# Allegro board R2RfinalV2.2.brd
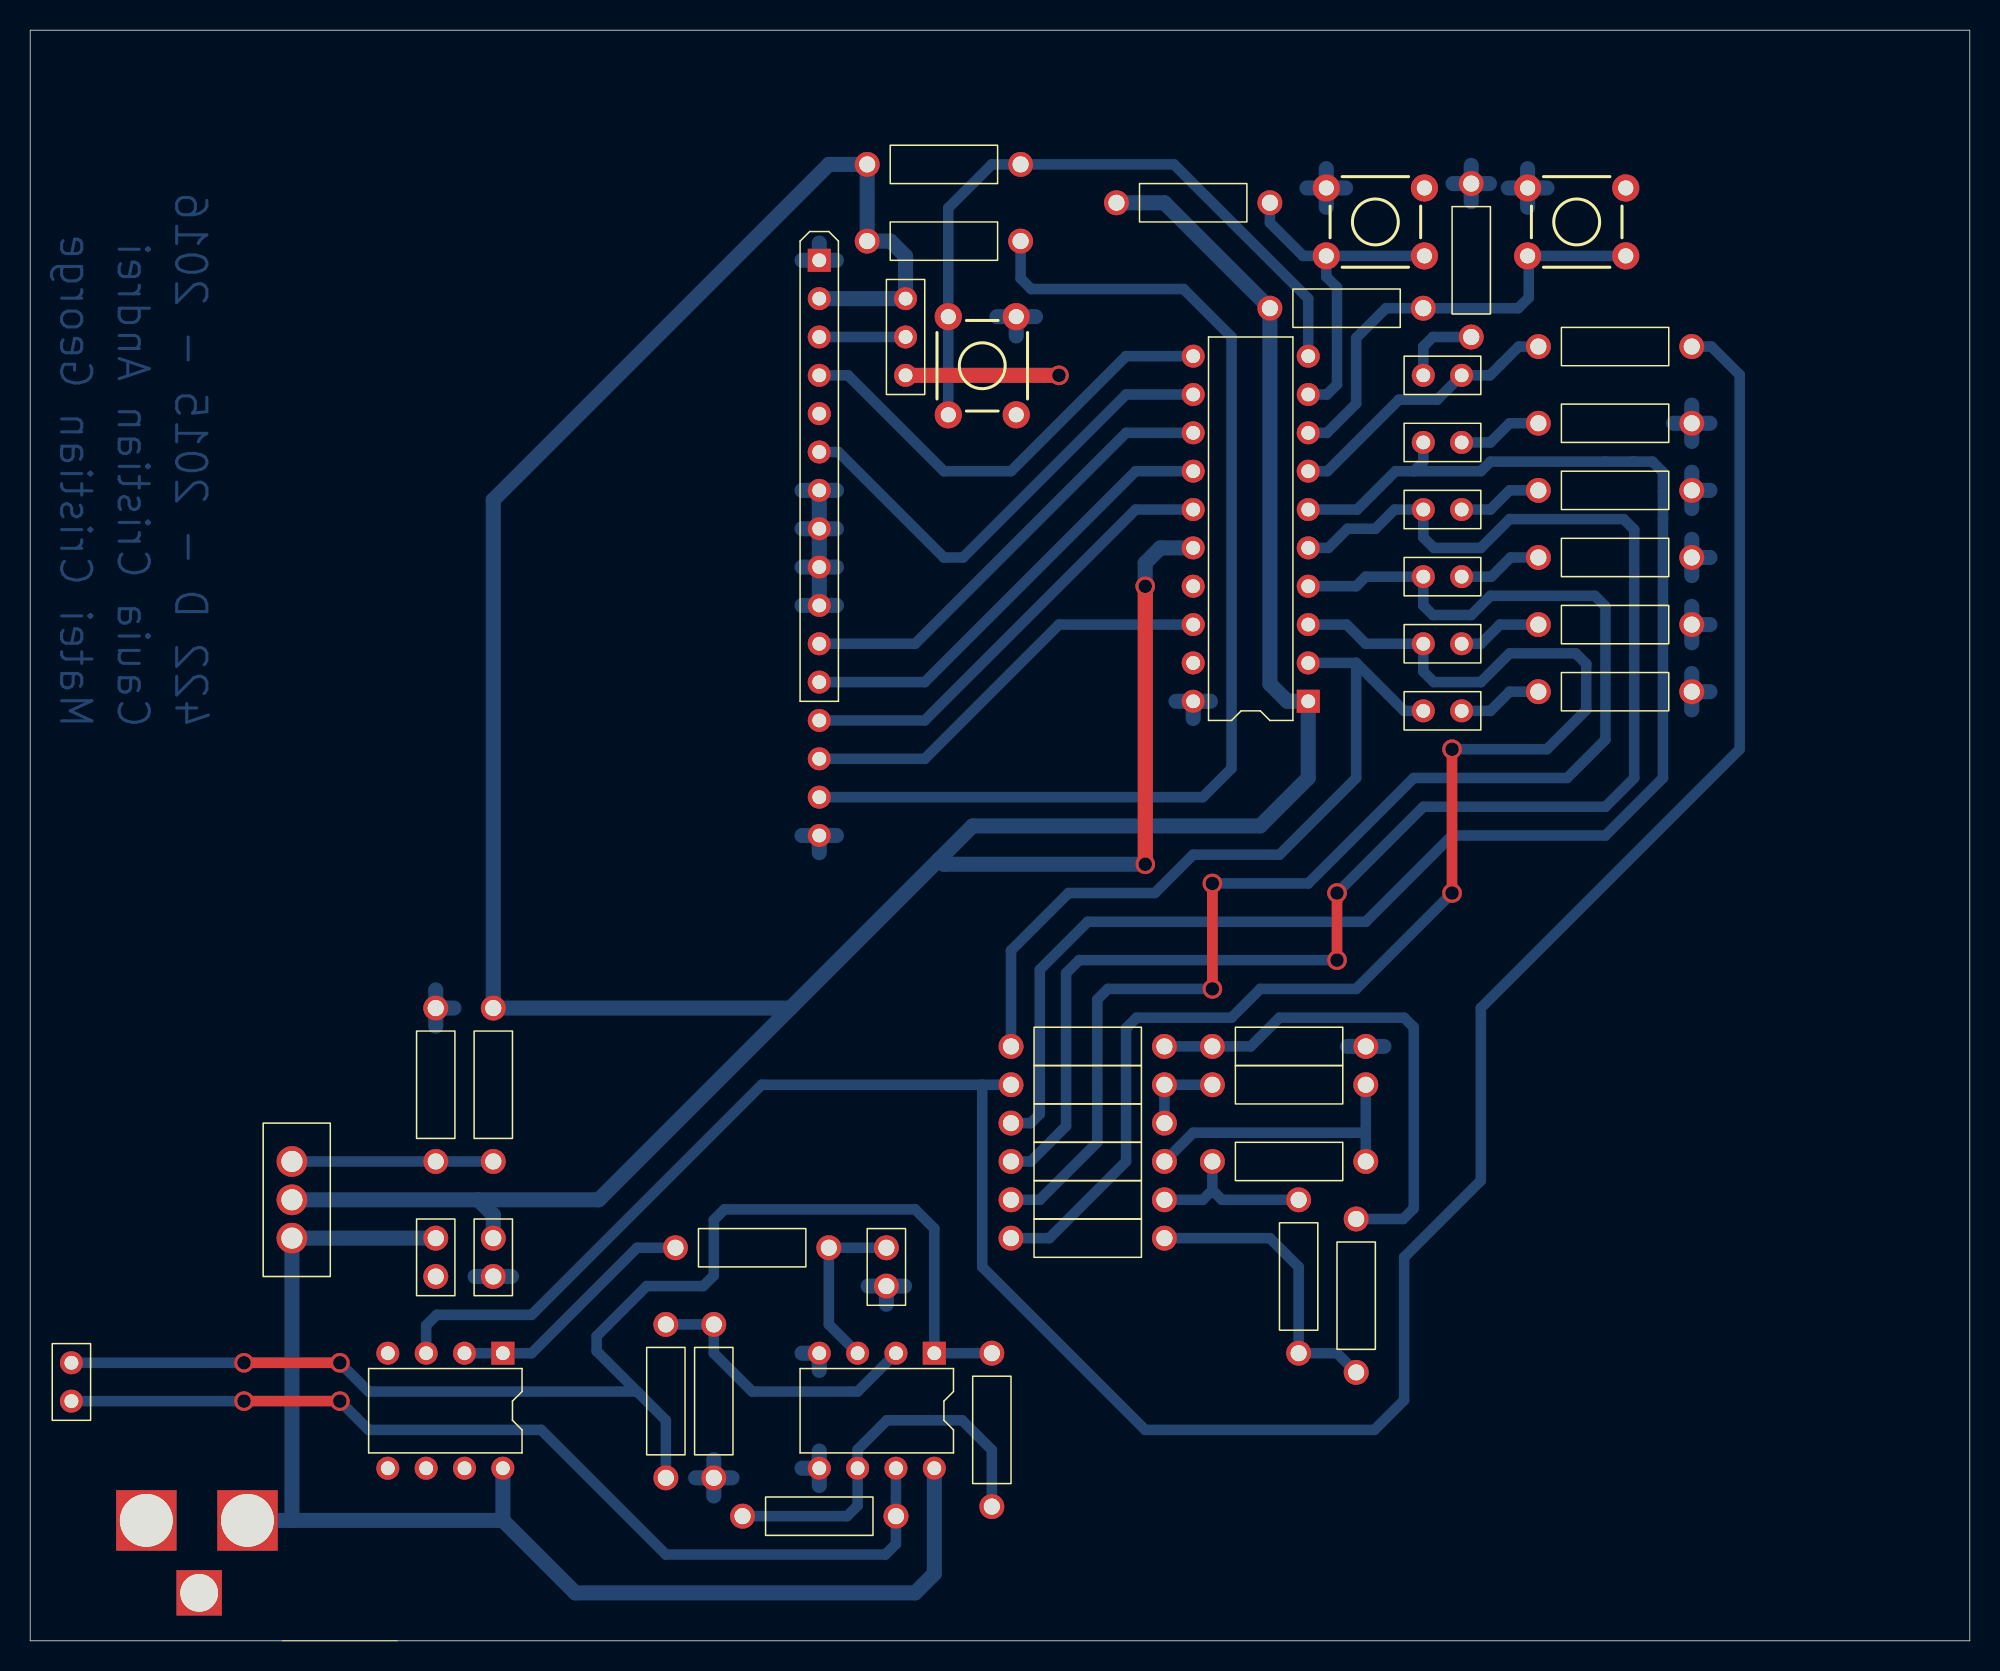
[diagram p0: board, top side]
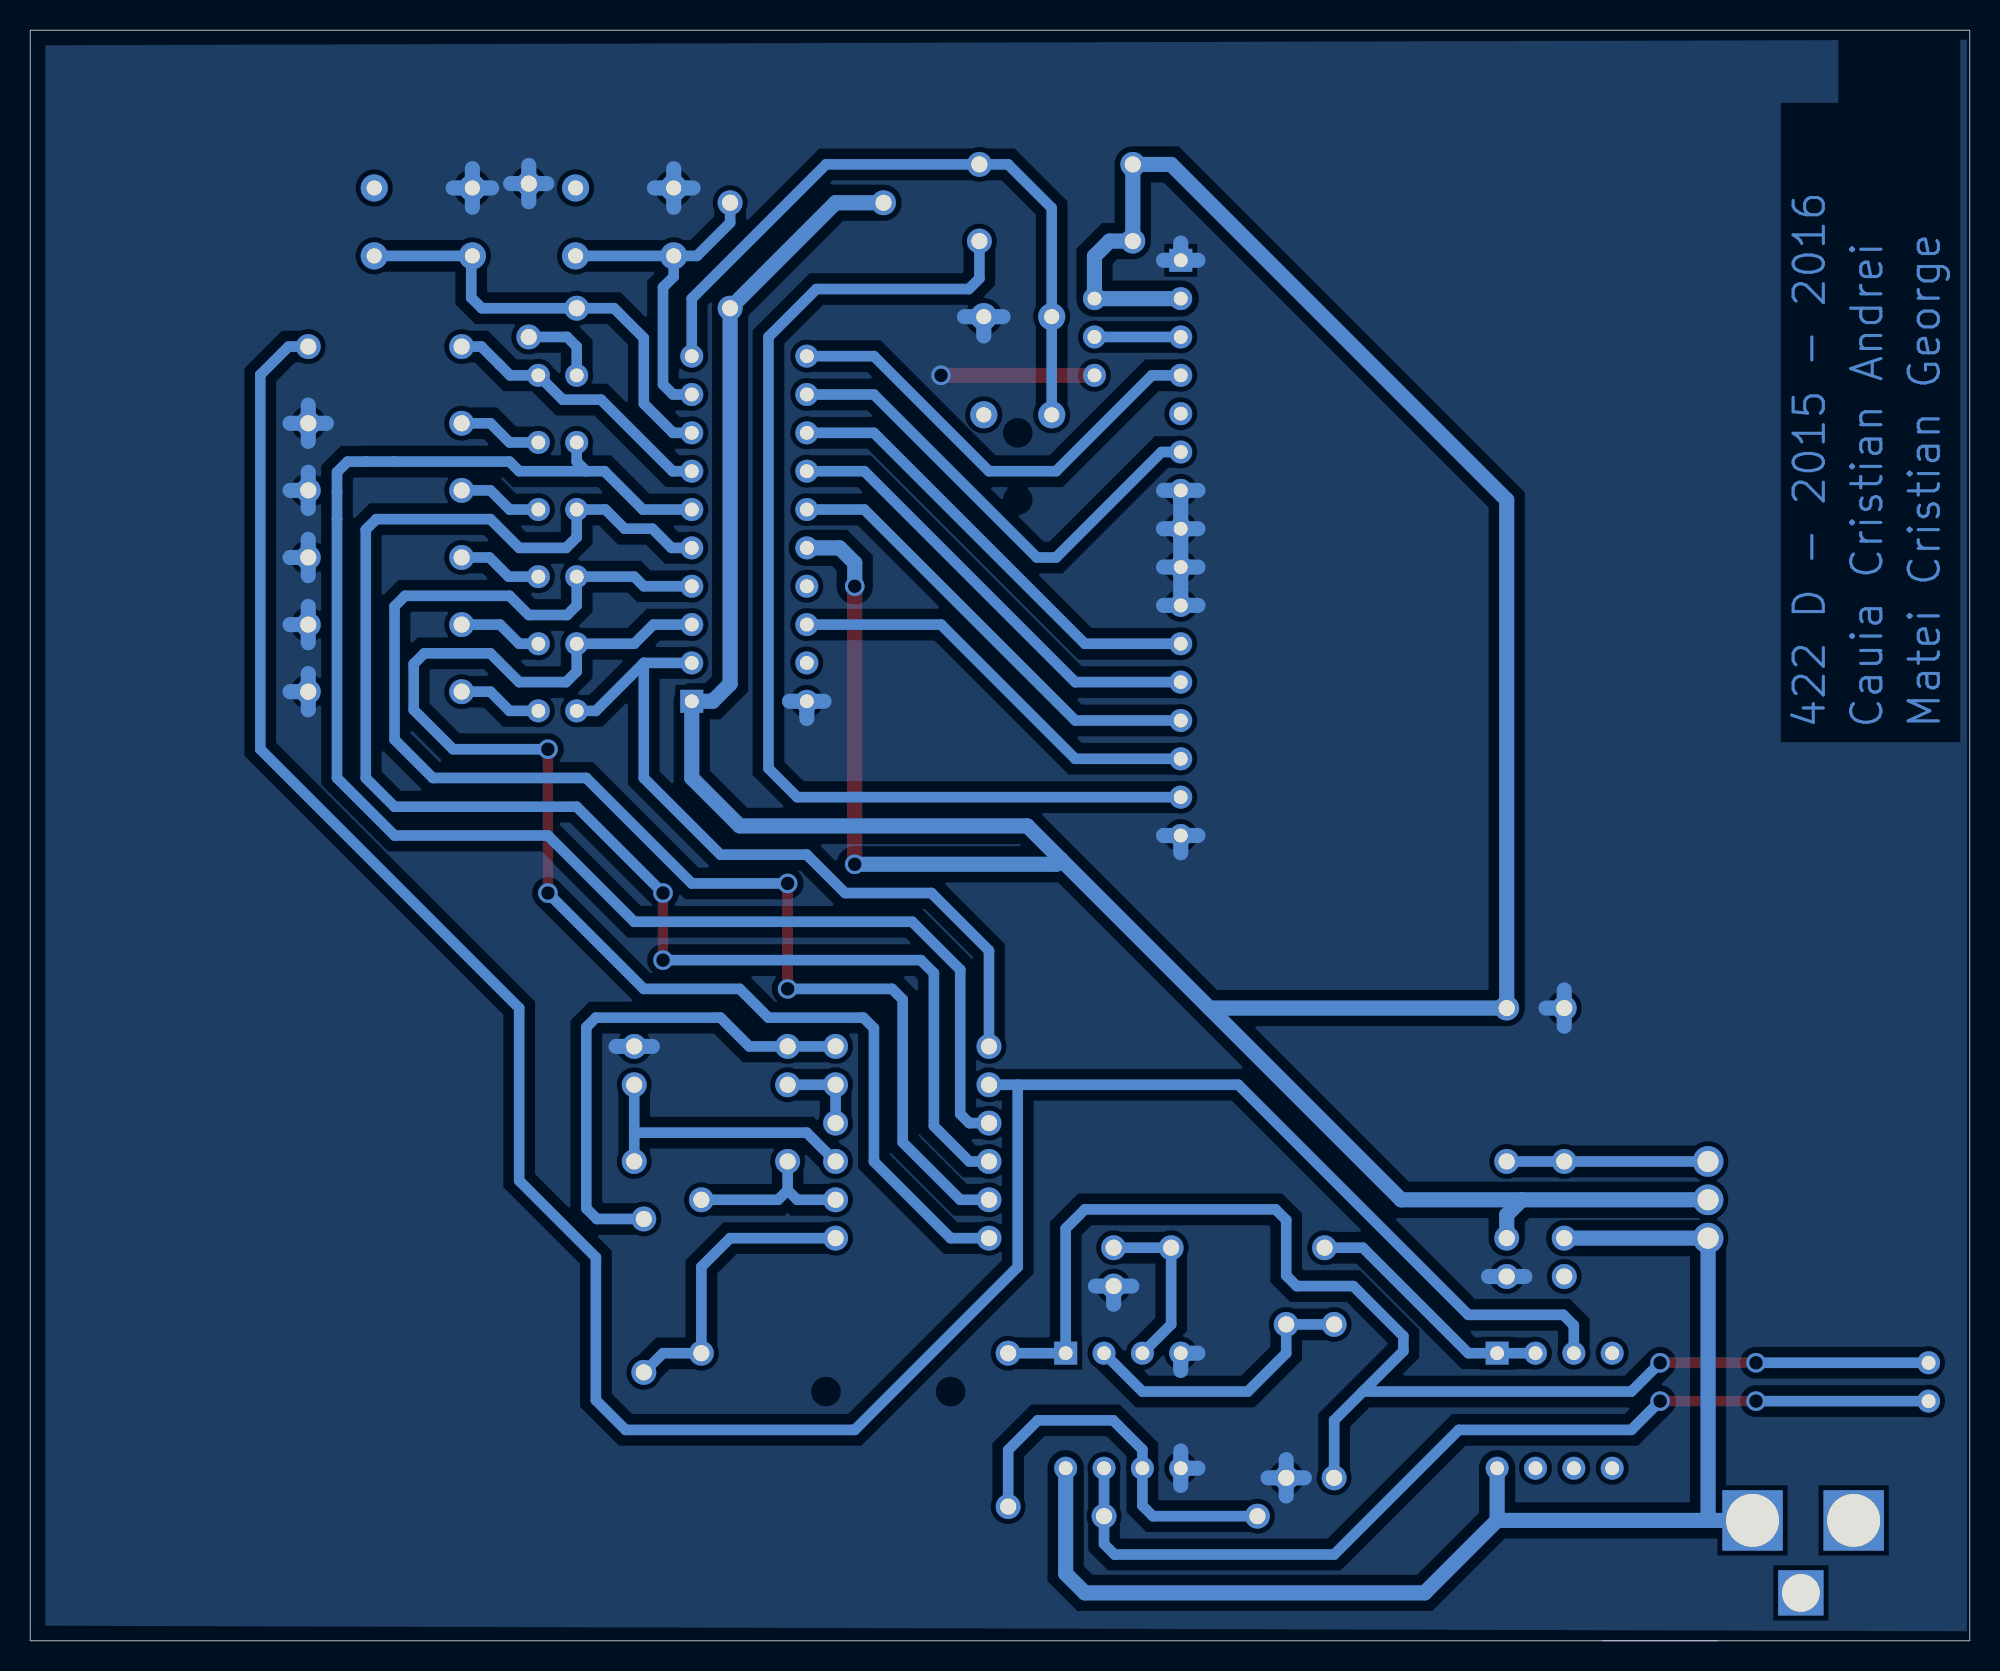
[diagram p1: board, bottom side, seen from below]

Outline 128.46 x 106.68 mm; copper layers: TOP, BOTTOM. Coordinates in mm from the lower left corner of the outline.
Outline path: 24.32,0 0,0 0,106.68 128.46,106.68 128.46,0 16.7,0

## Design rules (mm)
net group VCC: nets N20855 N35721 SW1 SW2 SW3 VCC
nets with their own width: min track width 0.7; nets N00328 N00336 N00340 N00355 N00395 N00470 N01662 N01669 N01683 N01690 N01717 N006340 N006500 N006660 N006820 N006980 N007140 N23488 N23661 N24189 N24193 N25824 N25853 N29134 N35057 N35516 N35592 N35638 N35656 N35674 N35692
nets with their own width: min track width 1; nets 0 9V

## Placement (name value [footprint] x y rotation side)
C3  10nf  [CAPCK05]  56.7 26.04 180 top
C4  10u  [CAPCK05]  26.86 24.13 0 top
C5  10u  [CAPCK05]  30.67 24.13 0 top
D1  MLED81  [JUMPER2]  94.81 83.82 180 top
D2  MLED81  [JUMPER2]  92.26 79.38 0 top
D3  MLED81  [JUMPER2]  92.26 74.93 0 top
D4  MLED81  [JUMPER2]  92.26 70.49 0 top
D5  MLED81  [JUMPER2]  92.26 66.04 0 top
D6  MLED81  [JUMPER2]  92.26 61.6 0 top
J1  Speaker  [JUMPER2]  2.73 18.42 270 top
J2  LCD 1602  [SIP16]  52.26 91.44 0 top
J3  CON3  [JACK_DC2]  0.19 3.18 0 top
R2  1k  [RES400]  75.12 36.83 90 top
R3  1k  [RES400]  88.45 36.83 90 top
R4  1k  [RES400]  78.3 31.75 270 top
R5  1k  [RES400]  84.01 19.05 0 top
R6  1k  [RES400]  87.82 27.94 180 top
R7  2k  [RES400]  64.96 39.37 270 top
R8  2k  [RES400]  64.96 26.67 270 top
R9  2k  [RES400]  64.96 29.21 270 top
R10  2k  [RES400]  64.96 31.75 270 top
R11  2k  [RES400]  64.96 34.29 270 top
R12  2k  [RES400]  99.88 85.73 270 top
R13  2k  [RES400]  88.45 39.37 90 top
R14  470  [RES400]  110.05 62.87 90 top
R15  470  [RES400]  110.05 67.31 90 top
R16  470  [RES400]  110.05 71.75 90 top
R17  470  [RES400]  110.05 76.2 90 top
R18  470  [RES400]  110.05 80.65 90 top
R19  470  [RES400]  95.44 96.52 180 top
R20  10k  [RES400]  45.27 20.96 180 top
R22  10k  [RES400]  63.69 8.89 0 top
R23  1k  [RES400]  26.86 41.91 180 top
R24  470  [RES400]  30.67 31.75 0 top
R26  33k  [RES400]  42.74 26.04 270 top
R27  10k  [RES400]  42.1 10.8 0 top
R28  10k  [RES400]  57.34 8.25 90 top
R29  1k  [JUMPER3]  57.98 83.82 90 top
R30  10k  [RES400]  65.6 97.79 90 top
R33  1k  [RES400]  55.44 92.71 270 top
R34  10k  [RES400]  82.11 95.25 90 top
R35  10k  [RES400]  92.26 88.27 90 top
SW7  SW_TC_SPST  [SW_SCHURTER_13019306L]  63.06 84.46 0 top
SW8  SW_TC_SPST  [SW_SCHURTER_13019306L]  89.09 93.98 90 top
SW9  SW_TC_SPST  [SW_SCHURTER_13019306L]  102.43 93.98 90 top
U1  MSP430G2553  [DIP20]  84.64 62.23 180 top
U7  LM317K  [TO220AB]  17.33 31.75 90 top
U9  LM358  [DIP8_3]  59.88 19.05 270 top
U10  LM358  [DIP8_3]  31.31 19.05 270 top

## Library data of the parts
C3 = C: Tolerance: ***; User Part Number: ***; signal model: DEFAULT_CAPACITOR_10000pF_1_2
C4 C5 = C: Tolerance: ***; User Part Number: ***; signal model: DEFAULT_CAPACITOR_1e+07pF_1_2
D1-D6 = MLED81: User Part Number: ***
J1 = CON2: User Part Number: ***
J2 = CON16: User Part Number: ***
J3 = CON3
R2-R6 R23 R33 = R: Tolerance: ***; User Part Number: ***; signal model: DEFAULT_RESISTOR_1000OHM_2_1
R7-R13 = R: Tolerance: ***; User Part Number: ***; signal model: DEFAULT_RESISTOR_2000OHM_2_1
R14-R19 R24 = R: Tolerance: ***; User Part Number: ***; signal model: DEFAULT_RESISTOR_470OHM_2_1
R20 R22 R27 R28 R30 R34 R35 = R: Tolerance: ***; User Part Number: ***; signal model: DEFAULT_RESISTOR_10000OHM_2_1
R26 = R: Tolerance: ***; User Part Number: ***; signal model: DEFAULT_RESISTOR_33000OHM_2_1
R29 = POT: User Part Number: ***
SW7-SW9 = SW_TC_SPST
U1 = MSP430G2553_4: Tolerance: ***; User Part Number: ***
U7 = LM317T_0
U9 = LM358: Tolerance: ***; User Part Number: ***
U10 = LM358_0: Tolerance: ***; User Part Number: ***

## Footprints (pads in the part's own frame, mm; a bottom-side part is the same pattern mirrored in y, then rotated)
CAPCK05
  round 1.651 hole 1.067: 1(0,0) 2(0,2.54)
DIP8_3
  rect 1.524x1.524 hole 0.914: 1(0,0)
  round 1.524 hole 0.914: 2(0,-2.54) 3(0,-5.08) 4(0,-7.62) 5(7.62,-7.62) 6(7.62,-5.08) 7(7.62,-2.54) 8(7.62,0)
DIP20
  rect 1.524x1.524 hole 0.914: 1(0,0)
  round 1.524 hole 0.914: 2(0,-2.54) 3(0,-5.08) 4(0,-7.62) 5(0,-10.16) 6(0,-12.7) 7(0,-15.24) 8(0,-17.78) 9(0,-20.32) 10(0,-22.86) 11(7.62,-22.86) 12(7.62,-20.32) 13(7.62,-17.78) 14(7.62,-15.24) 15(7.62,-12.7) 16(7.62,-10.16) 17(7.62,-7.62) 18(7.62,-5.08) 19(7.62,-2.54) 20(7.62,0)
JACK_DC2
  rect 4x4 hole 3.5: 1(14.2,4.8) 2(7.5,4.8)
  rect 3x3 hole 2.5: 3(11,0)
JUMPER2
  round 1.524 hole 0.914: 1(0,0) 2(2.54,0)
JUMPER3
  round 1.524 hole 0.914: 1(0,0) 2(2.54,0) 3(5.08,0)
RES400
  round 1.651 hole 1.067: 1(0,0) 2(0,10.16)
SIP16
  rect 1.524x1.524 hole 0.914: 1(0,0)
  round 1.524 hole 0.914: 2(0,-2.54) 3(0,-5.08) 4(0,-7.62) 5(0,-10.16) 6(0,-12.7) 7(0,-15.24) 8(0,-17.78) 9(0,-20.32) 10(0,-22.86) 11(0,-25.4) 12(0,-27.94) 13(0,-30.48) 14(0,-33.02) 15(0,-35.56) 16(0,-38.1)
SW_SCHURTER_13019306L
  round 1.8 hole 1: 1(-2.25,-3.25) 2(-2.25,3.25) 3(2.25,3.25) 4(2.25,-3.25)
TO220AB
  round 2.032 hole 1.397: 1(0,0) 2(-2.54,0) 3(-5.08,0)

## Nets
9V: C4.2 J3.1 U7.3(OUT) U9.8(V+) U10.8(V+)
VCC: C5.2 J2.2 R24.2 R29.3(2) R30.2 R33.1 R34.2 R35.2 U1.1(DVCC) U1.16(RESET) U7.2(IN)
0: C3.2 C4.1 C5.1 J2.1 J2.5 J2.7 J2.8 J2.9 J2.10 J2.16 J3.2 J3.3 R13.1 R14.1 R15.1 R16.1 R17.1 R18.1 R19.1 R20.2 R23.1 R29.1 SW7.3 SW8.3 SW9.3 U1.20(GROUND) U9.4(V-) U9.5(+) U10.4(V-)
SW1: R30.1 SW7.1 SW7.2 U1.10(P2_2)
SW2: R34.1 SW8.1 SW8.2 U1.9(P2_1)
SW3: R35.1 SW9.1 SW9.2 U1.8(P2_0/CS(B0))
N00328: R2.1 R3.2 R11.2
N00336: R4.1 R5.2 R9.2
N00340: R5.1 R6.2 R8.2
N00355: R2.2 R12.2 U10.3(+)
N00395: R3.1 R4.2 R10.2
N00470: R6.1 R7.2 R13.2
N01662: D5.1(A) R8.1 U1.3(P1_1/A1/RXD)
N01669: D4.1(A) R9.1 U1.4(P1_2/A2/TXD)
N01683: D2.1(A) R11.1 U1.6(P1_4/A4)
N01690: D1.1(A) R12.1 U1.7(P1_5/A5/SCK(B0))
N01717: D3.1(A) R10.1 U1.5(P1_3/A3/PUSH2)
N006340: D6.2(C) R14.2
N006500: D5.2(C) R15.2
N006660: D4.2(C) R16.2
N006820: D3.2(C) R17.2
N006980: D2.2(C) R18.2
N007140: D1.2(C) R19.2
N20855: R23.2 R24.1 U7.1(ADJ)
N23488: C3.1 R26.2 U9.3(+)
N23661: R26.1 U10.1(OUT) U10.2(-)
N24189: R20.1 R27.2 U9.2(-)
N24193: J1.1 R22.2 R27.1 U9.1(OUT)
N25824: R22.1 R28.2 U9.6(-)
N25853: J1.2 R28.1 U9.7(OUT)
N29134: D6.1(A) R7.1 U1.2(P1_0/A0/RED_LED)
N35057: J2.3 R29.2(T)
N35516: J2.4 U1.11(P2_3)
N35592: J2.6 U1.12(P2_4)
N35638: J2.11 U1.13(P2_5)
N35656: J2.12 U1.14(P1_6/A6/SCL/MISO(B0)/GREEN LED)
N35674: J2.13 U1.15(P1_7/A7/SDA/MOSE(B0))
N35692: J2.14 U1.18(P2_7/XOUT)
N35721: J2.15 R33.2

Pads without a net: SW7 4; SW8 4; SW9 4; U1 17 19; U10 5 6 7

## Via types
v1: diameter 1.3, hole 0.9, TOP to BOTTOM, 13 vias

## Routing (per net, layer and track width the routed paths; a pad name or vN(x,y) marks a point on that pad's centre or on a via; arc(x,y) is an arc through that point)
9V: length 86.7
  BOTTOM w1: 17.33,7.98 U7.3 C4.2 ; 17.33,7.98 J3.1 ; 17.33,7.98 31.31,7.98 ; U10.8 31.31,7.98 ; 31.31,7.98 36.11,3.18 58.61,3.18 59.88,4.44 U9.8
VCC: length 269.1
  TOP w1: v1(73.85,69.85) v1(73.85,51.44)
  BOTTOM w1: 60.2,51.75 62.42,53.98 81.47,53.98 84.64,57.15 U1.1 83.26,62.23 82.11,63.38 R35.2 75.12,95.25 R34.2 ; 60.2,51.75 50.36,41.91 ; 60.2,51.75 60.52,51.44 v1(73.85,51.44) ; 50.36,41.91 37.65,29.21 29.67,29.21 ; 50.36,41.91 R24.2 30.67,75.56 52.89,97.79 R30.2 R33.1 56.98,92.71 57.98,91.71 R29.3 J2.2 ; 29.67,29.21 U7.2 ; 29.67,29.21 30.67,28.21 C5.2 ; U1.16 74.85,72.39 73.85,71.39 v1(73.85,69.85)
0: length 97.2
  TOP w1: v1(68.13,83.82) R29.1 58.05,83.75
  BOTTOM w1: 55.5,23.5 C3.2 ; C3.2 57.91,23.5 ; C3.2 56.7,22.29 ; 97.9,96.23 SW9.3 ; SW9.3 100.45,96.23 ; SW9.3 99.18,97.51 ; SW9.3 99.18,94.95 ; 77.02,61.09 U1.20 ; U1.20 78.17,62.23 ; U1.20 75.88,62.23 ; 45.27,9.59 R20.2 ; R20.2 46.48,10.8 ; R20.2 45.27,12 ; R20.2 44.07,10.8 ; 108.84,80.65 R18.1 ; R18.1 110.05,81.85 ; R18.1 110.05,79.44 ; R18.1 111.25,80.65 ; R16.1 111.25,71.75 ; R16.1 110.05,70.55 ; R16.1 110.05,72.96 ; J2.8 53.4,73.66 ; J2.8 52.26,74.8 ; J2.8 51.12,73.66 ; J2.8 52.26,72.52 ; 52.26,75.06 J2.7 ; J2.7 51.12,76.2 ; J2.7 53.4,76.2 ; 51.12,53.34 J2.16 ; J2.16 52.26,52.2 ; J2.16 53.4,53.34 ; 110.05,61.66 R14.1 ; R14.1 111.25,62.87 ; R14.1 110.05,64.07 ; 51.12,71.12 J2.9 ; J2.9 52.26,72.26 ; J2.9 53.4,71.12 ; J2.9 52.26,69.98 ; 95.44,95.32 R19.1 ; R19.1 94.24,96.52 ; R19.1 95.44,97.72 ; R19.1 96.64,96.52 ; 110.05,75 R17.1 ; R17.1 110.05,77.4 ; R17.1 111.25,76.2 ; 52.26,17.91 U9.4 51.12,19.05 ; SW8.3 85.84,97.51 ; SW8.3 84.56,96.23 ; SW8.3 87.12,96.23 ; SW8.3 85.84,94.95 ; J2.1 53.4,91.44 ; J2.1 52.26,92.58 ; J2.1 51.12,91.44 ; J2.10 53.4,68.58 ; J2.10 52.26,69.72 ; J2.10 51.12,68.58 ; 110.05,66.11 R15.1 ; R15.1 110.05,68.51 ; R15.1 111.25,67.31 ; U9.5 52.26,12.57 ; U9.5 51.12,11.43 ; U9.5 52.26,10.29 ; 64.03,87.71 SW7.3 ; SW7.3 65.31,86.43 ; SW7.3 66.58,87.71 ; R23.1 28.06,41.91 ; R23.1 26.86,43.11 ; R23.1 26.86,40.71 ; 31.87,24.13 C5.1 29.47,24.13 ; 89.66,39.37 R13.1 87.25,39.37
SW1: length 46.2
  BOTTOM w0.7: U1.10 84.64,88.9 75.75,97.79 R30.1 63.69,97.79 60.81,94.91 SW7.2 SW7.1
SW2: length 23.5
  BOTTOM w0.7: U1.9 85.88,82.55 86.55,83.22 86.55,89.64 85.84,90.35 SW8.2 ; R34.1 82.11,93.93 84.3,91.73 SW8.2 ; SW8.2 SW8.1
SW3: length 30.2
  BOTTOM w0.7: U1.8 85.88,80.01 87.82,81.95 87.82,86.3 89.79,88.27 R35.1 98.55,88.27 99.25,88.97 99.25,91.66 SW9.2 SW9.1
N00328: length 5.7
  BOTTOM w0.7: 78.3,36.83 R2.1 R11.2
N00336: length 11.3
  BOTTOM w0.7: R4.1 78.3,29.85 ; 78.3,29.85 77.66,29.21 R9.2 ; 78.3,29.85 78.93,29.21 R5.2
N00340: length 19.7
  BOTTOM w0.7: R6.2 86.55,19.05 R5.1 84.01,24.77 82.11,26.67 R8.2
N00355: length 173.5
  BOTTOM w0.7: R12.2 111.35,85.73 113.22,83.85 113.22,59.06 96.07,41.91 96.07,30.48 91,25.4 91,15.94 89.02,13.97 73.85,13.97 63.06,24.77 63.06,36.83 ; 63.06,36.83 48.45,36.83 33.21,21.59 26.93,21.59 26.23,20.89 U10.3 ; 63.06,36.83 R2.2
N00395: length 19.2
  BOTTOM w0.7: R3.1 88.45,33.66 ; 88.45,33.66 77.02,33.66 R10.2 ; 88.45,33.66 R4.2
N00470: length 33.7
  BOTTOM w0.7: R6.1 90.93,27.94 91.63,28.64 91.63,40.64 91,41.28 82.74,41.28 80.83,39.37 R7.2
N01662: length 88.5
  TOP w0.7: v1(94.17,49.53) v1(94.17,59.06)
  BOTTOM w0.7: v1(94.17,49.53) 87.82,43.18 81.47,43.18 79.56,41.28 73.28,41.28 72.58,40.57 72.58,31.75 67.5,26.67 R8.1 ; v1(94.17,59.06) 100.45,59.06 103.06,61.66 103.06,64.71 102.36,65.41 97.98,65.41 96.07,63.5 92.96,63.5 92.26,64.2 D5.1 88.45,66.04 87.19,67.31 U1.3
N01669: length 93.4
  TOP w0.7: v1(78.3,43.18) v1(78.3,50.17)
  BOTTOM w0.7: v1(78.3,50.17) 84.64,50.17 91.63,57.15 101.79,57.15 104.33,59.69 104.33,68.52 103.63,69.22 96.71,69.22 95.44,67.94 92.9,67.94 92.26,68.58 D4.1 88.45,70.49 87.82,69.85 U1.4 ; R9.1 66.87,29.21 70.68,33.02 70.68,42.48 71.38,43.18 v1(78.3,43.18)
N01683: length 105.8
  BOTTOM w0.7: D2.1 92.26,78.11 91.63,77.47 ; 91.63,77.47 96.07,77.47 96.71,78.11 104.33,78.11 106.17,78.1 107.44,78.1 108.14,77.4 108.14,76.14 108.14,74.3 108.14,57.15 104.33,53.34 94.17,53.34 88.45,47.62 70.04,47.62 66.87,44.45 66.87,34.89 66.26,34.29 R11.1 ; 91.63,77.47 90.43,77.47 87.88,74.93 U1.6
N01690: length 18.7
  BOTTOM w0.7: R12.1 98.58,85.73 97.38,84.52 96.68,83.82 D1.1 93.19,82.21 90.65,82.21 85.92,77.47 U1.7
N01717: length 102.6
  TOP w0.7: v1(86.55,45.09) v1(86.55,49.53)
  BOTTOM w0.7: R10.1 66.26,31.75 68.61,34.1 68.61,44.22 69.47,45.09 v1(86.55,45.09) ; U1.5 85.98,72.39 87.25,73.66 89.09,73.66 90.36,74.93 D3.1 92.26,73.09 92.96,72.39 96.07,72.39 97.98,74.3 105.54,74.3 106.24,73.6 106.24,57.15 104.33,55.25 92.26,55.25 v1(86.55,49.53)
N006340: length 5.6
  BOTTOM w0.7: R14.2 97.98,62.87 96.71,61.6 D6.2
N006500: length 5.6
  BOTTOM w0.7: D5.2 96.07,66.04 97.35,67.31 R15.2
N006660: length 5.6
  BOTTOM w0.7: D4.2 96.77,70.49 98.05,71.75 R16.2
N006820: length 5.6
  BOTTOM w0.7: R17.2 97.98,76.2 96.71,74.93 D3.2
N006980: length 5.6
  BOTTOM w0.7: D2.2 96.71,79.38 97.98,80.65 R18.2
N007140: length 5.3
  BOTTOM w0.7: R19.2 92.9,86.36 92.26,85.73 D1.2
N20855: length 13.3
  BOTTOM w0.7: R24.1 R23.2 U7.1
N23488: length 11.6
  BOTTOM w0.7: U9.3 52.89,20.96 R26.2 C3.1
N23661: length 16.9
  BOTTOM w0.7: R26.1 40.19,26.04 33.21,19.05 U10.1 U10.2
N24189: length 19.2
  BOTTOM w0.7: U9.2 54.8,16.51 47.81,16.51 45.27,19.05 R20.1 R27.2
N24193: length 90.1
  TOP w0.7: v1(20.51,18.42) v1(14.16,18.42)
  BOTTOM w0.7: v1(20.51,18.42) 22.41,16.51 40.19,16.51 ; 40.19,16.51 37.51,19.19 37.51,20.18 40.83,23.5 44.57,23.5 45.27,24.19 45.27,27.88 45.98,28.57 58.61,28.57 59.88,27.31 U9.1 R22.2 ; 40.19,16.51 42.1,14.61 R27.1 ; v1(14.16,18.42) J1.1
N25824: length 25.9
  BOTTOM w0.7: R28.2 54.1,8.25 54.8,8.96 U9.6 54.8,12.67 56.74,14.61 61.72,14.61 63.69,12.63 R22.1
N25853: length 64.1
  TOP w0.7: v1(20.51,15.88) v1(14.16,15.88)
  BOTTOM w0.7: v1(20.51,15.88) 22.42,13.97 33.85,13.97 42.1,5.72 56.64,5.72 57.34,6.42 R28.1 U9.7 ; v1(14.16,15.88) J1.2
N29134: length 50.5
  BOTTOM w0.7: U1.2 87.82,64.77 ; 87.82,64.77 87.82,57.15 82.74,52.07 77.02,52.07 74.49,49.53 68.77,49.53 64.96,45.72 R7.1 ; 87.82,64.77 91,61.6 D6.1
N35057: length 5.7
  BOTTOM w0.7: J2.3 R29.2
N35516: length 30.6
  BOTTOM w0.7: U1.11 72.58,85.09 64.96,77.47 60.51,77.47 54.17,83.82 J2.4
N35592: length 32.1
  BOTTOM w0.7: J2.6 53.53,78.74 60.51,71.75 61.79,71.75 72.58,82.55 U1.12
N35638: length 30.6
  BOTTOM w0.7: U1.13 72.58,80.01 58.61,66.04 J2.11
N35656: length 30.6
  BOTTOM w0.7: U1.14 73.21,77.47 59.25,63.5 J2.12
N35674: length 30.6
  BOTTOM w0.7: U1.15 73.21,74.93 59.25,60.96 J2.13
N35692: length 28.4
  BOTTOM w0.7: U1.18 68.13,67.31 59.25,58.42 J2.14
N35721: length 74.7
  BOTTOM w0.7: J2.15 77.66,55.88 79.56,57.79 79.56,86.36 76.39,89.54 66.3,89.54 65.6,90.24 R33.2

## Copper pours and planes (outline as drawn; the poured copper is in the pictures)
0 on BOTTOM: 0.19,0.63 0.19,106.05 127.46,105.68 127.46,1

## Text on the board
BOTTOM: Matei Cristian George | Cauia Cristian Andrei | 422 D - 2015 - 2016
